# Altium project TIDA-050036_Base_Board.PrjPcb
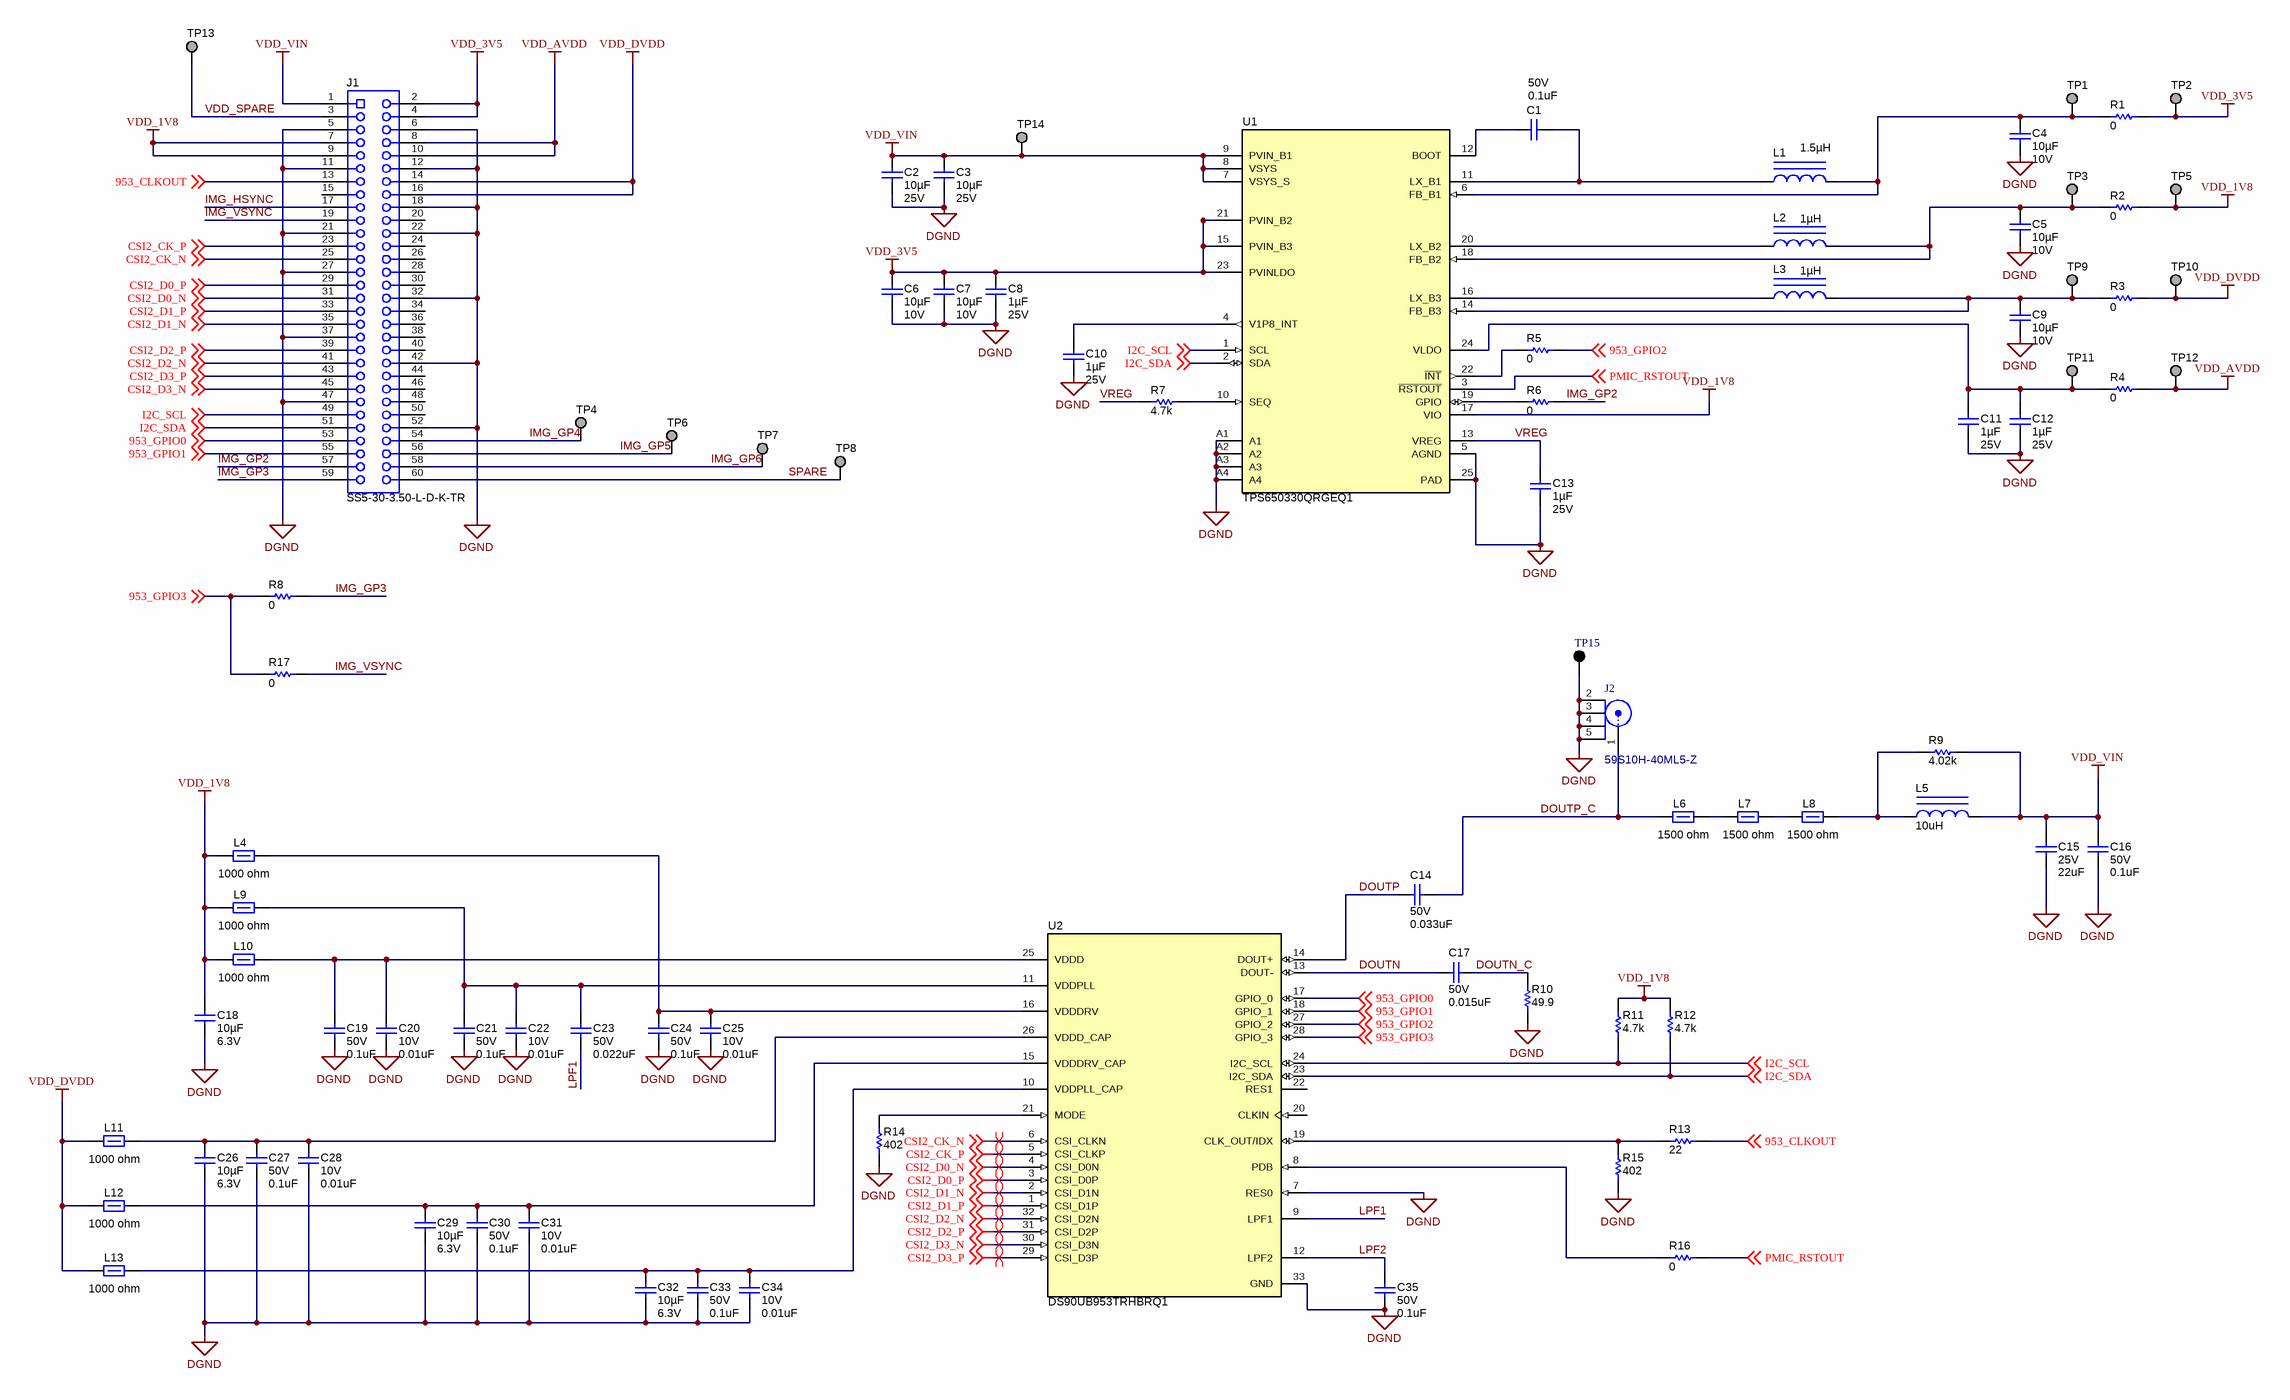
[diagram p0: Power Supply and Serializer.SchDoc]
CopyrightYear: 2018; PCB_Layout: Who did the Layout?; PCB_Rev: E1; PRJ_Customer: Public Release; PRJ_Engineer: Gerard Copeland; PRJ_Number: TIDA-050036; PRJ_Title: TIDA-050036_Base_Board; SCH_Rev: E1; TechSupport: http://www.ti.com/support
2 sheets, 92 parts. Net scope: global (net labels, ports and power ports of the same name join across sheets).
Board file: Power Supply and Serializer.PcbDoc
Sheets:
  Power Supply and Serializer.SchDoc
  Hardware.SchDoc

## Sheet Power Supply and Serializer.SchDoc: Power Supply and Serializer
size A2; Date: Not shown in title block; ApprovedBy: Not shown in title block; CheckedBy: Not shown in title block; Author: Not shown in title block; CompanyName: Not shown in title block; DrawnBy: Gerard Copeland; Engineer: Not shown in title block; Organization: Not shown in title block; Address1: Not shown in title block; Address2: Not shown in title block; Address3: Not shown in title block; Address4: Not shown in title block; DocumentNumber: 2; Revision: Use project parameter SCH_Rev; SheetNumber: 1; SheetTotal: 2; PageSetup: Record=PageOptions¦CenterHorizontal=True¦CenterVertical=True¦PrintScale=1.00¦XCorrection=1.00¦YCorrection=1.00¦PrintKind=0¦BorderSize=5000000¦LeftOffset=0¦BottomOffset=0¦Orientation=2¦PaperLength=1000¦PaperWidth=1000¦Scale=100¦PaperSource=15¦PrintQuality=600¦MediaType=1¦DitherType=10¦PaperKind=Letter¦PrintScaleMode=1; System: Connector

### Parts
C1  VDC_V: 50V  ValueDisplayed: 0.1uF  [0402S]  (hidden comment: CGA2B3X7R1H104K050BB)
C2  ValueDisplayed: 10µF  VDC_V: 25V  [1206_190]  (hidden comment: CGA5L1X7R1E106K160AE)
C3  ValueDisplayed: 10µF  VDC_V: 25V  [1206_190]  (hidden comment: CGA5L1X7R1E106K160AE)
C4  Cap_F: 10µF  VDC_V: 10V  [0805L]  (hidden comment: C0805C106J8RACAUTO)
C5  Cap_F: 10µF  VDC_V: 10V  [0805L]  (hidden comment: C0805C106J8RACAUTO)
C6  Cap_F: 10µF  VDC_V: 10V  [0805L]  (hidden comment: C0805C106J8RACAUTO)
C7  Cap_F: 10µF  VDC_V: 10V  [0805L]  (hidden comment: C0805C106J8RACAUTO)
C8  Cap_F: 1µF  VDC_V: 25V  [0603S]  (hidden comment: CGA3E1X7R1E105K080AC)
C9  Cap_F: 10µF  VDC_V: 10V  [0805L]  (hidden comment: C0805C106J8RACAUTO)
C10  Cap_F: 1µF  VDC_V: 25V  [0603S]  (hidden comment: CGA3E1X7R1E105K080AC)
C11  Cap_F: 1µF  VDC_V: 25V  [0603S]  (hidden comment: CGA3E1X7R1E105K080AC)
C12  Cap_F: 1µF  VDC_V: 25V  [0603S]  (hidden comment: CGA3E1X7R1E105K080AC)
C13  Cap_F: 1µF  VDC_V: 25V  [0603S]  (hidden comment: CGA3E1X7R1E105K080AC)
C14  VDC_V: 50V  ValueDisplayed: 0.033uF  [0402S]  (hidden comment: CGA2B3X7R1H333K050BB)
C15  VDC_V: 25V  ValueDisplayed: 22uF  [1206_190L]  (hidden comment: C3216X5R1E226M160AB)
C16  VDC_V: 50V  ValueDisplayed: 0.1uF  [0402S]  (hidden comment: CGA2B3X7R1H104K050BB)
C17  VDC_V: 50V  ValueDisplayed: 0.015uF  [0402S]  (hidden comment: CGA2B3X7R1H153K050BB)
C18  Cap_F: 10µF  VDC_V: 6.3V  [0805L]  (hidden comment: GCM21BR70J106KE22L)
C19  VDC_V: 50V  ValueDisplayed: 0.1uF  [0402S]  (hidden comment: CGA2B3X7R1H104K050BB)
C20  VDC_V: 10V  ValueDisplayed: 0.01uF  [0201_033]  (hidden comment: CGA1A2X7R1A103K030BA)
C21  VDC_V: 50V  ValueDisplayed: 0.1uF  [0402S]  (hidden comment: CGA2B3X7R1H104K050BB)
C22  VDC_V: 10V  ValueDisplayed: 0.01uF  [0201_033]  (hidden comment: CGA1A2X7R1A103K030BA)
C23  VDC_V: 50V  ValueDisplayed: 0.022uF  [0402S]  (hidden comment: GCM155R71H223KA55D)
C24  VDC_V: 50V  ValueDisplayed: 0.1uF  [0402S]  (hidden comment: CGA2B3X7R1H104K050BB)
C25  VDC_V: 10V  ValueDisplayed: 0.01uF  [0201_033]  (hidden comment: CGA1A2X7R1A103K030BA)
C26  Cap_F: 10µF  VDC_V: 6.3V  [0805L]  (hidden comment: GCM21BR70J106KE22L)
C27  VDC_V: 50V  ValueDisplayed: 0.1uF  [0402S]  (hidden comment: CGA2B3X7R1H104K050BB)
C28  VDC_V: 10V  ValueDisplayed: 0.01uF  [0201_033]  (hidden comment: CGA1A2X7R1A103K030BA)
C29  Cap_F: 10µF  VDC_V: 6.3V  [0805L]  (hidden comment: GCM21BR70J106KE22L)
C30  VDC_V: 50V  ValueDisplayed: 0.1uF  [0402S]  (hidden comment: CGA2B3X7R1H104K050BB)
C31  VDC_V: 10V  ValueDisplayed: 0.01uF  [0201_033]  (hidden comment: CGA1A2X7R1A103K030BA)
C32  Cap_F: 10µF  VDC_V: 6.3V  [0805L]  (hidden comment: GCM21BR70J106KE22L)
C33  VDC_V: 50V  ValueDisplayed: 0.1uF  [0402S]  (hidden comment: CGA2B3X7R1H104K050BB)
C34  VDC_V: 10V  ValueDisplayed: 0.01uF  [0201_033]  (hidden comment: CGA1A2X7R1A103K030BA)
C35  VDC_V: 50V  ValueDisplayed: 0.1uF  [0402S]  (hidden comment: CGA2B3X7R1H104K050BB)
J1  SS5-30-3.50-L-D-K-TR  [Samtec_SS5-30-3_50-x-D-K]
J2  59S10H-40ML5-Z  [Rosenberger_59S10H-40ML5-Z]
L1  ValueDisplayed: 1.5µH  [TFM201610ALMA]  (hidden comment: TFM201610ALMA1R5MTAA)
L2  ValueDisplayed: 1µH  [TFM201610ALMA]  (hidden comment: TFM201610ALMA1R0MTAA)
L3  ValueDisplayed: 1µH  [TFM201610ALMA]  (hidden comment: TFM201610ALMA1R0MTAA)
L4  value 1000 ohm  [0402S]  (hidden comment: BLM15AG102SN1D)
L5  ValueDisplayed: 10uH  [LQH3NPZ_JR]  (hidden comment: LQH3NPZ100MJRL)
L6  value 1500 ohm  [0603S]  (hidden comment: BLM18HE152SN1D)
L7  value 1500 ohm  [0603S]  (hidden comment: BLM18HE152SN1D)
L8  value 1500 ohm  [0603S]  (hidden comment: BLM18HE152SN1D)
L9  value 1000 ohm  [0402S]  (hidden comment: BLM15AG102SN1D)
L10  value 1000 ohm  [0402S]  (hidden comment: BLM15AG102SN1D)
L11  value 1000 ohm  [0402S]  (hidden comment: BLM15AG102SN1D)
L12  value 1000 ohm  [0402S]  (hidden comment: BLM15AG102SN1D)
L13  value 1000 ohm  [0402S]  (hidden comment: BLM15AG102SN1D)
R1  ValueDisplayed: 0  [0402]  (hidden comment: ERJ-2GE0R00X)
R2  ValueDisplayed: 0  [0402]  (hidden comment: ERJ-2GE0R00X)
R3  ValueDisplayed: 0  [0402]  (hidden comment: ERJ-2GE0R00X)
R4  ValueDisplayed: 0  [0402]  (hidden comment: ERJ-2GE0R00X)
R5  ValueDisplayed: 0  [0402L]  (hidden comment: ERJ-2GE0R00X)
R6  ValueDisplayed: 0  [0402L]  (hidden comment: ERJ-2GE0R00X)
R7  ValueDisplayed: 4.7k  [0402S]  (hidden comment: CRCW04024K70JNED)
R8  ValueDisplayed: 0  [0402S]  (hidden comment: ERJ-2GE0R00X)
R9  ValueDisplayed: 4.02k  [0402S]  (hidden comment: CRCW04024K02FKED)
R10  ValueDisplayed: 49.9  [0201]  (hidden comment: CRCW020149R9FKED)
R11  ValueDisplayed: 4.7k  [0402S]  (hidden comment: CRCW04024K70JNED)
R12  ValueDisplayed: 4.7k  [0402S]  (hidden comment: CRCW04024K70JNED)
R13  ValueDisplayed: 22  [0201]  (hidden comment: ERJ-1GNJ220C)
R14  ValueDisplayed: 402  [0402S]  (hidden comment: CRCW0402402RFKED)
R15  ValueDisplayed: 402  [0402S]  (hidden comment: CRCW0402402RFKED)
R16  ValueDisplayed: 0  [0402S]  (hidden comment: ERJ-2GE0R00X)
R17  ValueDisplayed: 0  [0402S]  (hidden comment: ERJ-2GE0R00X)
TP1  TP_H0.45P0.75  [TP_H045P075]  (value not drawn)  (no BOM)
TP2  TP_H0.45P0.75  [TP_H045P075]  (value not drawn)  (no BOM)
TP3  TP_H0.45P0.75  [TP_H045P075]  (value not drawn)  (no BOM)
TP4  TP_H0.45P0.75  [TP_H045P075]  (value not drawn)  (no BOM)
TP5  TP_H0.45P0.75  [TP_H045P075]  (value not drawn)  (no BOM)
TP6  TP_H0.45P0.75  [TP_H045P075]  (value not drawn)  (no BOM)
TP7  TP_H0.45P0.75  [TP_H045P075]  (value not drawn)  (no BOM)
TP8  TP_H0.45P0.75  [TP_H045P075]  (value not drawn)  (no BOM)
TP9  TP_H0.45P0.75  [TP_H045P075]  (value not drawn)  (no BOM)
TP10  TP_H0.45P0.75  [TP_H045P075]  (value not drawn)  (no BOM)
TP11  TP_H0.45P0.75  [TP_H045P075]  (value not drawn)  (no BOM)
TP12  TP_H0.45P0.75  [TP_H045P075]  (value not drawn)  (no BOM)
TP13  TP_H0.45P0.75  [TP_H045P075]  (value not drawn)  (no BOM)
TP14  TP_H0.45P0.75  [TP_H045P075]  (value not drawn)  (no BOM)
TP15  5001  [Keystone5001]  (value not drawn)
U1  TPS650330QRGEQ1  [RGE0024K]
U2  DS90UB953TRHBRQ1  [RHB0032P]

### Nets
DGND: C2.2 C3.2 C4.2 C5.2 C6.2 C7.2 C8.2 C9.2 C10.2 C11.2 C12.2 C13.2 C15.2 C16.2 C18.1 C19.2 C20.2 C21.2 C22.2 C24.2 C25.2 C26.2 C27.2 C28.2 C29.2 C30.2 C31.2 C32.2 C33.2 C34.2 C35.2 J1.5 J1.6 J1.11 J1.12 J1.18 J1.21 J1.22 J1.27 J1.32 J1.37 J1.42 J1.47 J1.52 J2.2 J2.3 J2.4 J2.5 R10.1 R14.1 R15.1 TP15.1 U1.5(AGND) U1.25(PAD) U1.A1 U1.A2 U1.A3 U1.A4 U2.7(RES0) U2.33(GND)
VDD_1V8: C18.2 J1.7 J1.9 L4.1 L9.1 L10.1 R2.2 R11.2 R12.2 TP5.1 U1.17(VIO)
VDD_3V5: C6.1 C7.1 C8.1 J1.2 J1.4 R1.2 TP2.1 U1.15(PVIN_B3) U1.21(PVIN_B2) U1.23(PVINLDO)
VDD_AVDD: J1.8 J1.10 R4.1 TP12.1
VDD_DVDD: J1.14 J1.16 L11.1 L12.1 L13.1 R3.2 TP10.1
VDD_VIN: C2.1 C3.1 C15.1 C16.1 J1.1 L5.2 R9.2 TP14.1 U1.7(VSYS_S) U1.8(VSYS) U1.9(PVIN_B1)
953_CLKOUT: J1.13 R13.1 ; off-sheet 953_CLKOUT
953_GPIO0: J1.53 U2.17(GPIO_0) ; off-sheet 953_GPIO0
953_GPIO1: J1.55 U2.18(GPIO_1) ; off-sheet 953_GPIO1
953_GPIO2: R5.1 U2.27(GPIO_2) ; off-sheet 953_GPIO2
953_GPIO3: R8.1 R17.1 U2.28(GPIO_3) ; off-sheet 953_GPIO3
CSI2_CK_N: J1.25 U2.6(CSI_CLKN) ; off-sheet CSI2_CK_N
CSI2_CK_P: J1.23 U2.5(CSI_CLKP) ; off-sheet CSI2_CK_P
CSI2_D0_N: J1.31 U2.4(CSI_D0N) ; off-sheet CSI2_D0_N
CSI2_D0_P: J1.29 U2.3(CSI_D0P) ; off-sheet CSI2_D0_P
CSI2_D1_N: J1.35 U2.2(CSI_D1N) ; off-sheet CSI2_D1_N
CSI2_D1_P: J1.33 U2.1(CSI_D1P) ; off-sheet CSI2_D1_P
CSI2_D2_N: J1.41 U2.32(CSI_D2N) ; off-sheet CSI2_D2_N
CSI2_D2_P: J1.39 U2.31(CSI_D2P) ; off-sheet CSI2_D2_P
CSI2_D3_N: J1.45 U2.30(CSI_D3N) ; off-sheet CSI2_D3_N
CSI2_D3_P: J1.43 U2.29(CSI_D3P) ; off-sheet CSI2_D3_P
DOUTN: C17.1 U2.13(DOUT-)
DOUTN_C: C17.2 R10.2
DOUTP: C14.1 U2.14(DOUT+)
DOUTP_C: C14.2 J2.1 L6.1
I2C_SCL: J1.49 R11.1 U1.1(SCL) U2.24(I2C_SCL) ; off-sheet I2C_SCL
I2C_SDA: J1.51 R12.1 U1.2(SDA) U2.23(I2C_SDA) ; off-sheet I2C_SDA
IMG_GP2: J1.57 R6.1
IMG_GP3: J1.59 R8.2
IMG_GP4: J1.54 TP4.1
IMG_GP5: J1.56 TP6.1
IMG_GP6: J1.58 TP7.1
IMG_HSYNC: J1.17
IMG_VSYNC: J1.19 R17.2
LPF1: C23.2 U2.9(LPF1)
LPF2: C35.1 U2.12(LPF2)
PMIC_RSTOUT: R16.1 U1.3(~{RSTOUT}) ; off-sheet PMIC_RSTOUT
SPARE: J1.60 TP8.1
VDD_SPARE: J1.3 TP13.1
VREG: C13.1 R7.1 U1.13(VREG)
NetC1_1: C1.1 L1.1 U1.11(LX_B1)
NetC1_2: C1.2 U1.12(BOOT)
NetC4_1: C4.1 L1.2 R1.1 TP1.1 U1.6(FB_B1)
NetC5_1: C5.1 L2.2 R2.1 TP3.1 U1.18(FB_B2)
NetC9_1: C9.1 L3.2 R3.1 TP9.1 U1.14(FB_B3)
NetC10_1: C10.1 U1.4(V1P8_INT)
NetC11_1: C11.1 C12.1 R4.2 TP11.1 U1.24(VLDO)
NetC19_1: C19.1 C20.1 L10.2 U2.25(VDDD)
NetC21_1: C21.1 C22.1 C23.1 L9.2 U2.11(VDDPLL)
NetC24_1: C24.1 C25.1 L4.2 U2.16(VDDDRV)
NetC26_1: C26.1 C27.1 C28.1 L11.2 U2.26(VDDD_CAP)
NetC29_1: C29.1 C30.1 C31.1 L12.2 U2.15(VDDDRV_CAP)
NetC32_1: C32.1 C33.1 C34.1 L13.2 U2.10(VDDPLL_CAP)
NetL2_1: L2.1 U1.20(LX_B2)
NetL3_1: L3.1 U1.16(LX_B3)
NetL5_1: L5.1 L8.2 R9.1
NetL6_2: L6.2 L7.1
NetL7_2: L7.2 L8.1
NetR5_2: R5.2 U1.22(~{INT})
NetR6_2: R6.2 U1.19(GPIO)
NetR7_2: R7.2 U1.10(SEQ)
NetR13_2: R13.2 R15.2 U2.19(CLK_OUT/IDX)
NetR14_2: R14.2 U2.21(MODE)
NetR16_2: R16.2 U2.8(PDB)

Not connected (* = marked no-connect by the designer): J1 15 20 24 26 28 30 34 36 38 40 44 46 48 50; U2 20(CLKIN) 22(RES1)

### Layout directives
differential pair: CSI2_CK_N, CSI2_CK_P, CSI2_D0_N, CSI2_D0_P, CSI2_D1_N, CSI2_D1_P, CSI2_D2_N, CSI2_D2_P, CSI2_D3_N, CSI2_D3_P

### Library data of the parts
C1 C16 C19 C21 C24 C27 C30 C33 C35 = CMP-0006325-2: CAP, CERM, 0.1 uF, 50 V, +/- 10%, X7R, AEC-Q200 Grade 1, 0402; Manufacturer: TDK; TaMin_C: -55°C; ESR_ohm: 0.039064; Polarized: N; SizeAreaWB_mm2: 3; Value1: 0.039064 ohm; U/M: EA; Value: 0.1uF; TaMax_C: 125°C; SizeZ_mm: 0.6; SizeX_mm: 1; SizeY_mm: 0.5; Cap_Case: 0402; AEC Qualified: Y; Cap_F: 100nF; IRMS_A: 814.669mA; AEC Category: Q200
C2 C3 = CMP-0085253-1: CAP, CERM, 10 µF, 25 V,+/- 10%, X7R, AEC-Q200 Grade 1, 1206; Manufacturer: TDK; AEC Qualified: Y; Polarized: N; SizeAreaWB_mm2: 10.92; TaMax_C: 125°C; Value: 10uF; AEC Category: Q200; TaMin_C: -55°C; U/M: EA; SizeY_mm: 1.6; SizeArea_mm2: 5.12; AEC Grade: 1; SizeZ_mm: 1.9; Cap_Case: 1206; SizeX_mm: 3.2
C4-C7 C9 = CMP-0081061-1: CAP, CERM, 10 µF, 10 V,+/- 5%, X7R, AEC-Q200 Grade 1, 0805; Manufacturer: Kemet; TaMin_C: -55°C; Polarized: N; SizeAreaWB_mm2: 6.75; U/M: EA; Value: 10uF; TaMax_C: 125°C; SizeZ_mm: 1.45; SizeX_mm: 2; SizeY_mm: 1.25; Cap_Case: 0805; SizeArea_mm2: 2.5; AEC Qualified: Y; AEC Grade: 1; AEC Category: Q200
C8 C10-C13 = CMP-0076705-3: CAP, CERM, 1 µF, 25 V,+/- 10%, X7R, AEC-Q200 Grade 1, 0603; Manufacturer: TDK; SizeAreaWB_mm2: 4.68; SizeArea_mm2: 1.28; AEC Qualified: Y; AEC Category: Q200; Value: 1uF; TaMax_C: 125°C; SizeZ_mm: 1.0; AEC Grade: 1; Polarized: N; TaMin_C: -55°C; SizeY_mm: 0.8; U/M: EA; SizeX_mm: 1.6; Cap_Case: 1.6x0.8x0.8mm
C14 = CMP-0006329-2: CAP, CERM, 0.033 uF, 50 V, +/- 10%, X7R, AEC-Q200 Grade 1, 0402; Manufacturer: TDK; TaMin_C: -55°C; ESR_ohm: 0.098477; Polarized: N; SizeAreaWB_mm2: 3; Value1: 0.098477 ohm; U/M: EA; TaMax_C: 125°C; SizeZ_mm: 0.6; SizeX_mm: 1; SizeY_mm: 0.5; Cap_Case: 0402; AEC Qualified: Y; Cap_F: 33nF; IRMS_A: 530.78mA; AEC Category: Q200
C15 = CMP-0008654-2: CAP, CERM, 22 uF, 25 V, +/- 20%, X5R, 1206_190; Manufacturer: TDK; TaMin_C: -55°C; Polarized: N; SizeAreaWB_mm2: 10.92; Value1: Unknown; U/M: EA; Value: 22uF; TaMax_C: 85°C; SizeZ_mm: 1.9; SizeX_mm: 3.2; SizeY_mm: 1.6; Cap_Case: 1206; SizeArea_mm2: 5.12; Cap_F: 22µF; AEC Category: Q200
C17 = CMP-0006327-2: CAP, CERM, 0.015 uF, 50 V, +/- 10%, X7R, AEC-Q200 Grade 1, 0402; Manufacturer: TDK; TaMin_C: -55°C; ESR_ohm: 0.2162; Polarized: N; SizeAreaWB_mm2: 3; Value1: 0.2162 ohm; U/M: EA; TaMax_C: 125°C; SizeZ_mm: 0.6; SizeX_mm: 1; SizeY_mm: 0.5; Cap_Case: 0402; AEC Qualified: Y; Cap_F: 15nF; IRMS_A: 379.389mA; AEC Category: Q200
C18 C26 C29 C32 = CMP-0008016-2: CAP, CERM, 10 uF, 6.3 V, +/- 10%, X7R, AEC-Q200 Grade 1, 0805; Manufacturer: MuRata; TaMin_C: -55°C; Polarized: N; SizeAreaWB_mm2: 6.75; Value1: Unknown; U/M: EA; Value: 10uF; TaMax_C: 125°C; SizeZ_mm: 1.45; SizeX_mm: 2; SizeY_mm: 1.25; Cap_Case: 0805; SizeArea_mm2: 2.5; AEC Qualified: Y; AEC Grade: 1; AEC Category: Q200
C20 C22 C25 C28 C31 C34 = CMP-0009642-3: CAP, CERM, 0.01 uF, 10 V, +/- 10%, X7R, AEC-Q200 Grade 1, 0201; Manufacturer: TDK; TaMin_C: -55°C; ESR_ohm: 0.280214; Polarized: N; SizeAreaWB_mm2: 2.08; Value1: 0.280214 ohm; U/M: EA; Value: 0.01uF; TaMax_C: 125°C; SizeZ_mm: 0.33; SizeX_mm: 0.6; SizeY_mm: 0.3; SizeArea_mm2: 0.18; AEC Qualified: Y; Cap_F: 10nF; IRMS_A: 245.718mA; AEC Grade: 1; AEC Category: Q200
C23 = CMP-0006358-2: CAP, CERM, 0.022 uF, 50 V, +/- 10%, C0G/NP0, 0402; Manufacturer: MuRata; TaMin_C: -55°C; Polarized: N; SizeAreaWB_mm2: 3; Value1: Unknown; U/M: EA; TaMax_C: 125°C; SizeZ_mm: 0.6; SizeX_mm: 1; SizeY_mm: 0.5; Cap_Case: 0402; Cap_F: 22nF; AEC Category: Q200
J1 = CMP-0055621-1: Receptacle, 0.5mm, 30x2, Gold, SMT; Manufacturer: Samtec; CNHeader: FALSE; Current_A: 1.5A; Gender: Female; Row_Count: 2; Pitch_mm: 0.5; System: Connector
J2 = CMP-0075127-1: Connector, HF, 50 Ohm, TH; Manufacturer: Rosenberger; CNHeader: False; Green_Lifecycle: Not Set; Gender: Male; Green_REACh: Incomplete; ContactFinish: Gold
L1 = CMP-0081093-1: Inductor, Shielded, Metal Composite, 1.5 µH, 2.3 A, 0.11 ohm, AEC-Q200 Grade 0, SMD; Manufacturer: TDK; Isat: 2.8A @ 30% inductance drop; Irms: 2.3A @ 40C rise; SizeAreaWB_mm2: 7.8; DCR_ohm: 0.11; Value: 1.5uH; Imax_A: 2.3A; SizeZ_mm: 1; SizeX_mm: 2; SizeY_mm: 1.6; SizeArea_mm2: 3.2; AEC Qualified: Y; AEC Grade: 0; AEC Category: Q200
L2 L3 = CMP-0081092-1: Inductor, Shielded, Metal Composite, 1 µH, 3.1 A, 0.06 ohm, AEC-Q200 Grade 0, SMD; Manufacturer: TDK; Isat: 3.3A @ 30% inductance drop; Irms: 3.1A @ 40C rise; SizeAreaWB_mm2: 7.8; DCR_ohm: 0.06; Value: 1uH; Imax_A: 3.1A; SizeZ_mm: 1; SizeX_mm: 2; SizeY_mm: 1.6; SizeArea_mm2: 3.2; AEC Qualified: Y; AEC Grade: 0; AEC Category: Q200
L4 L9-L13 = CMP-0003310-1: Ferrite Bead, 1000 ohm @ 100 MHz, 0.3 A, 0402; Manufacturer: MuRata; ZTyp@100MHz_Ohm: 1k; SizeAreaWB_mm2: 3; DCR_ohm: 0.65; Value1: 0.65 ohm; Imax_A: 300mA; SizeZ_mm: 0.6; SizeX_mm: 1; SizeY_mm: 0.5; Value2: 0.3A
L5 = CMP-0058702-1: Inductor, Wirewound, Ferrite, 10 uH, 0.81 A, 0.288 ohm, AEC-Q200 Grade 1, SMD; Manufacturer: MuRata; Isat: 0.81A @ 30% inductance drop; Irms: 1.2A @ 40C rise; SizeAreaWB_mm2: 16; DCR_ohm: 0.288; Value: 10uH; Imax_A: 810mA; SizeZ_mm: 1.2; SizeX_mm: 3; Value2: 0.81A; SizeArea_mm2: 9; Ind_H: 10µH; AEC Qualified: Y; AEC Grade: 1; AEC Category: Q200
L6-L8 = CMP-0003349-2: Ferrite Bead, 1500 ohm @ 100 MHz, 0.5 A, 0603; Manufacturer: MuRata; Ztyp@1GHz_Ohm: 1.5k; SizeAreaWB_mm2: 4.68; DCR_ohm: 0.5; Value1: 0.5 ohm; Imax_A: 500mA; SizeZ_mm: 1; SizeX_mm: 1.6; SizeY_mm: 0.8; Value2: 0.5A; SizeArea_mm2: 1.28
R1-R6 R8 R16 R17 = CMP-0026992-3: RES, 0, 5%, 0.1 W, AEC-Q200 Grade 0, 0402; Manufacturer: Panasonic; Power_W: 100mW; TempCo: 600 ppm/C; Value_Code: 0000; Value: 0; EIA_Code: E24; SizeX_mm: 1; SizeY_mm: 0.5; SizeZ_mm: 0.6; Value2: 0.1W; AEC Qualified: Y; VDC_V: 50V; AEC Category: Q200; SizeAreaWB_mm2: 3
R7 R11 R12 = CMP-0026938-5: RES, 4.7 k, 5%, 0.063 W, AEC-Q200 Grade 0, 0402; Manufacturer: Vishay-Dale; Power_W: 63mW; TempCo: 200 ppm/C; Value_Code: 4k70; Value: 4.7k; EIA_Code: E24; SizeX_mm: 1; SizeY_mm: 0.5; SizeZ_mm: 0.6; Value2: 0.063W; AEC Qualified: Y; VDC_V: 50V; AEC Category: Q200; AEC Grade: 0
R9 = CMP-0026405-2: RES, 4.02 k, 1%, 0.063 W, AEC-Q200 Grade 0, 0402; Manufacturer: Vishay-Dale; Power_W: 63mW; TempCo: 100 ppm/C; Value_Code: 4k02; Value: 4.02k; EIA_Code: E96; SizeX_mm: 1; SizeY_mm: 0.5; SizeZ_mm: 0.6; Value2: 0.063W; AEC Qualified: Y; VDC_V: 50V; AEC Category: Q200; AEC Grade: 0
R10 = CMP-0027279-3: RES, 49.9, 1%, 0.05 W, 0201; Manufacturer: Vishay-Dale; Power_W: 50mW; TempCo: 100 ppm/C; Value_Code: 49R9; Value: 49.9; EIA_Code: E96; SizeX_mm: 0.6; SizeY_mm: 0.3; SizeZ_mm: 0.26; Value2: 0.05W; SizeArea_mm2: 0.18; AEC Qualified: N; VDC_V: 30V; AEC Category: Q200
R13 = CMP-0027015-3: RES, 22, 5%, 0.05 W, AEC-Q200 Grade 1, 0201; Manufacturer: Panasonic; Power_W: 50mW; TempCo: 200 ppm/C; Value_Code: 22R0; U/M: EA; Value: 22; EIA_Code: E24; SizeX_mm: 0.6; SizeY_mm: 0.3; SizeZ_mm: 0.26; Value2: 0.05W; SizeArea_mm2: 0.18; AEC Qualified: Y; AEC Grade: 1; AEC Category: Q200
R14 R15 = CMP-0026366-2: RES, 402, 1%, 0.063 W, AEC-Q200 Grade 0, 0402; Manufacturer: Vishay-Dale; Power_W: 63mW; TempCo: 100 ppm/C; Value_Code: 402R; Value: 402; EIA_Code: E96; SizeX_mm: 1; SizeY_mm: 0.5; SizeZ_mm: 0.6; Value2: 0.063W; AEC Qualified: Y; VDC_V: 50V; AEC Category: Q200; AEC Grade: 0
TP1-TP14 = CMP-0003719-1: Testpoint; Manufacturer: Texas Instruments; CompType: Pad
TP15 = CMP-0055138-1: Test Point, Miniature, Black, TH; Manufacturer: Keystone; CNHeader: FALSE; Green_Lifecycle: Active; Green_REACh: Passed; ContactFinish: Silver; CT: TRUE
U1 = CMP-0080054-3: Automotive Camera PMIC, RGE0024K (VQFN-24); Manufacturer: Texas Instruments; SizeAreaWB_mm2: 25; SizeArea_mm2: 16; AEC Qualified: Y; AEC Category: Q200; SizeZ_mm: 1; SizeY_mm: 4; CompType: IC
U2 = CMP-0084098-1: 2MP MIPI CSI-2 FPD-Link III Serializer for 2MP/60fps Cameras and RADAR, RHB0032P (VQFN-32); Manufacturer: Texas Instruments; Alternate PartNumber: DS90UB953TRHBTQ1; Rating: Automotive; SizeAreaWB_mm2: 49; SizeArea_mm2: 25; AEC Qualified: Y; AEC Category: Q200; SizeZ_mm: 1; SizeY_mm: 5; CompType: IC

## Sheet Hardware.SchDoc: Hardware
size 431 x 279 mm; Date: Not shown in title block; ApprovedBy: Not shown in title block; CheckedBy: Not shown in title block; Author: Not shown in title block; CompanyName: Not shown in title block; DrawnBy: Gerard Copeland; Engineer: Not shown in title block; Organization: Not shown in title block; Address1: Not shown in title block; Address2: Not shown in title block; Address3: Not shown in title block; Address4: Not shown in title block; DocumentNumber: 3; Revision: Use project parameter SCH_Rev; SheetNumber: 2; SheetTotal: 2; PageSetup: Record=PageOptions¦CenterHorizontal=True¦CenterVertical=True¦PrintScale=1.00¦XCorrection=1.00¦YCorrection=1.00¦PrintKind=0¦BorderSize=5000000¦LeftOffset=0¦BottomOffset=0¦Orientation=2¦PaperLength=1000¦PaperWidth=1000¦Scale=100¦PaperSource=15¦PrintQuality=600¦MediaType=1¦DitherType=10¦PaperKind=Letter¦PrintScaleMode=1
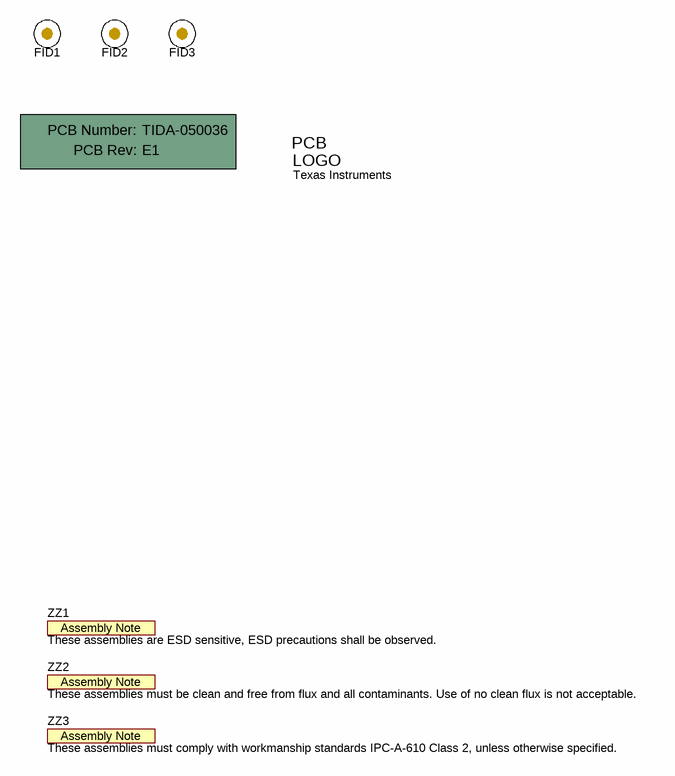
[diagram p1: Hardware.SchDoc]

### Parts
!PCB1  Printed Circuit Board  (value not drawn)  (mechanical)
FID1  Fiducial  [Fiducial10-20]  (value not drawn)
FID2  Fiducial  [Fiducial10-20]  (value not drawn)
FID3  Fiducial  [Fiducial10-20]  (value not drawn)
Logo2  Texas Instruments  [TI_Symbol_Overlay_Small]  (no BOM)
ZZ1  These assemblies are ESD sensitive, ESD precautions shall be observed.  [AssemblyNote]  (no BOM)
ZZ2  These assemblies must be clean and free from flux and all contaminants. Use of no clean flux is not acceptable.  [AssemblyNote]  (no BOM)
ZZ3  These assemblies must comply with workmanship standards IPC-A-610 Class 2, unless otherwise specified.  [AssemblyNote]  (no BOM)

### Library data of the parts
!PCB1 = CMP-0003618-2: Manufacturer: Any; PartNumber: TIDA-050036
FID1-FID3 = CMP-0077181-1: Fiducial mark.  There is nothing to buy or mount.
Logo2 = CMP-0074838-1: Texas Instrument Corporate Signature; SymbolCreator: a0412235; Lib Reference: TI_Logo; Library Reference: Logo
ZZ1 = CMP-0077236-1
ZZ2 = CMP-0077237-1
ZZ3 = CMP-0077238-1

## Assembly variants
001: not fitted FID1 FID2 FID3 R17 TP1 TP2 TP3 TP4 TP5 TP6 TP7 TP8 TP9 TP10 TP11 TP12 TP13 TP14 TP15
